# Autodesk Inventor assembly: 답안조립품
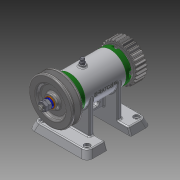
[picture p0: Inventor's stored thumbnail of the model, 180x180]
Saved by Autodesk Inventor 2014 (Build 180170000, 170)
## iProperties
Created: 2016-07
Part Number: 답안조립품
Document SubType Name: Assembly
Designer: Administrator
Author: Administrator
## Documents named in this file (14)
- C:\Users\Administrator\Desktop\460707V1003\답안조립품.iam
- C:\Users\Administrator\Desktop\460707V1003\본체.ipt
- C:\Users\Administrator\Desktop\460707V1003\커버.ipt
- C:\Users\Administrator\Desktop\460707V1003\볼트 M4 x 12.ipt
- C:\Users\Administrator\Desktop\460707V1003\오일 실 15 25 7.ipt
- C:\Users\Administrator\Desktop\460707V1003\베어링 15 x 32 x 9.ipt
- C:\Users\Administrator\Desktop\460707V1003\축.ipt
- C:\Users\Administrator\Desktop\460707V1003\키 3 x 3 x 12.ipt
- C:\Users\Administrator\Desktop\460707V1003\V벨트풀리.ipt
- C:\Users\Administrator\Desktop\460707V1003\와셔 8x17.ipt
- C:\Users\Administrator\Desktop\460707V1003\스프링와셔 8.ipt
- C:\Users\Administrator\Desktop\460707V1003\너트 M 8.ipt
- C:\Users\Administrator\Desktop\460707V1003\스퍼기어.ipt
- C:\Users\Administrator\Desktop\460707V1003\니플 M 6 x 0.75.ipt
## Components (11 placed, 3 different names)
1. KS B 2023 6002 - 15 x 32 x 9:1
2. KS B 2023 6002 - 15 x 32 x 9:2
3. V벨트풀리:1
4. ISO 4762 M4 x 12:1
5. ISO 4762 M4 x 12:2
6. ISO 4762 M4 x 12:3
7. ISO 4762 M4 x 12:4
8. ISO 4762 M4 x 12:5
9. ISO 4762 M4 x 12:6
10. ISO 4762 M4 x 12:7
11. ISO 4762 M4 x 12:8
